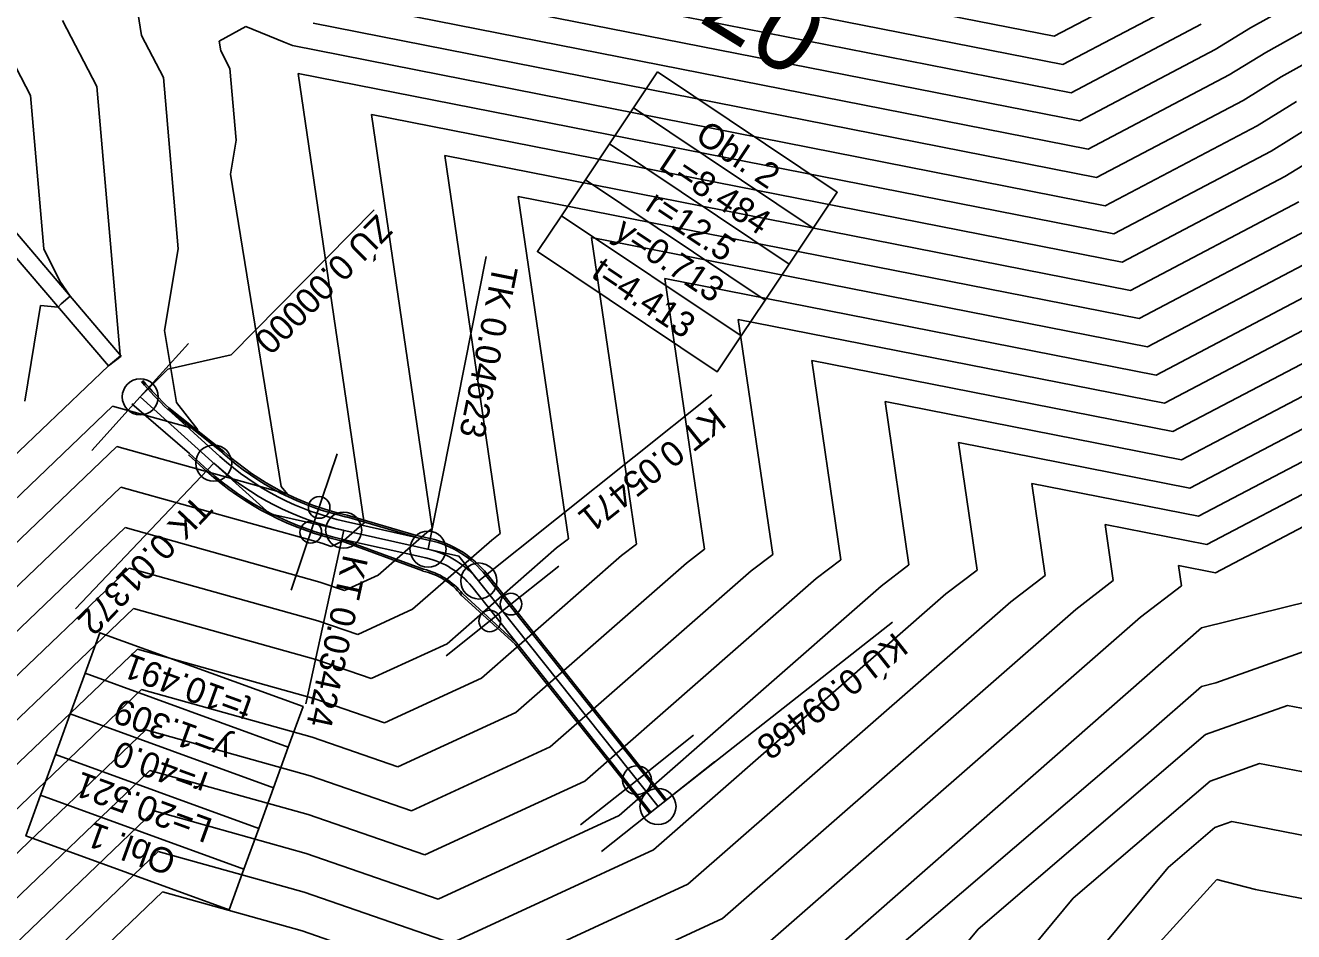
# Model space of a CAD drawing. Extents: x -549394 to -546608, y -1037055 to -1033629.
# Drawn here: x -547395.5 to -547219.5, y -1036140.1 to -1036014.3 of the extents above; entities that cross this region are included whole.
import ezdxf

# ---------------------------------------------------------------- set-up
doc = ezdxf.new("R2010")
doc.units = 0
for name, color, linetype in [('hlavni_vrst', 7, 'Continuous'), ('hrana_L', 7, 'Continuous'), ('norm_vrst', 7, 'Continuous'), ('POLYGONY_SITUACE_PO', 7, 'Continuous'), ('u_sirka_0_5m', 7, 'Continuous'), ('u_sirka_1_5m', 7, 'Continuous'), ('x_navrh_C411', 7, 'Continuous'), ('x_osa_C411', 7, 'Continuous'), ('x_popis_oblouky_C411', 7, 'Continuous'), ('x_popis_pricne_rezy_C411', 7, 'Continuous'), ('x_popis_velky_C411', 7, 'Continuous')]:
    doc.layers.add(name, color=color, linetype=linetype)

msp = doc.modelspace()

# ---------------------------------------------------------------- linework, layer by layer
at = {"layer": 'hlavni_vrst'}
for p, q in [((-547171.43, -1035989.1), (-547223.36, -1036018.08)), ((-547248.01, -1036031.52), (-547352.65, -1036010.92)), ((-547390.31, -1036013.64), (-547385.56, -1036022.8)), ((-547223.36, -1036018.08), (-547228.45, -1036021.22)), ((-547228.45, -1036021.22), (-547248.01, -1036031.52)), ((-547385.56, -1036022.8), (-547382.3, -1036060.1)), ((-547337.27, -1036032.37), (-547329.59, -1036084.85)), ((-547242.13, -1036051.11), (-547337.27, -1036032.37)), ((-547218.78, -1036038.81), (-547242.13, -1036051.11)), ((-547209.1, -1036056.41), (-547236.25, -1036070.69)), ((-547383.95, -1036061.55), (-547529.34, -1036200.56)), ((-547382.26, -1036060.17), (-547383.95, -1036061.55)), ((-547383.95, -1036061.55), (-547383.95, -1036061.55)), ((-547383.95, -1036061.55), (-547383.95, -1036061.55)), ((-547383.95, -1036061.55), (-547383.95, -1036061.55)), ((-547383.95, -1036061.55), (-547383.95, -1036061.55)), ((-547383.95, -1036061.55), (-547383.95, -1036061.55)), ((-547383.95, -1036061.55), (-547383.95, -1036061.55)), ((-547383.95, -1036061.55), (-547383.95, -1036061.55)), ((-547382.3, -1036060.1), (-547382.27, -1036060.15)), ((-547382.27, -1036060.15), (-547382.26, -1036060.17)), ((-547286.38, -1036060.82), (-547282.33, -1036088.47)), ((-547236.25, -1036070.69), (-547286.38, -1036060.82)), ((-547206.64, -1036077.79), (-547230.36, -1036090.28)), ((-547330.76, -1036085.74), (-547341.74, -1036095.35)), ((-547329.59, -1036084.85), (-547330.76, -1036085.74)), ((-547381.07, -1036089.63), (-547506.12, -1036209.19)), ((-547354.88, -1036096.94), (-547381.07, -1036089.63)), ((-547282.33, -1036088.47), (-547285.75, -1036091.08)), ((-547235.49, -1036089.27), (-547235.08, -1036092.1)), ((-547230.36, -1036090.28), (-547235.49, -1036089.27)), ((-547285.75, -1036091.08), (-547317.86, -1036119.19)), ((-547235.08, -1036092.1), (-547240.75, -1036096.43)), ((-547349.34, -1036098.86), (-547354.88, -1036096.94)), ((-547341.74, -1036095.35), (-547349.34, -1036098.86)), ((-547240.75, -1036096.43), (-547293.98, -1036143.02)), ((-547378.19, -1036117.71), (-547482.89, -1036217.82)), ((-547356.25, -1036123.83), (-547378.19, -1036117.71)), ((-547317.86, -1036119.19), (-547340.07, -1036129.43)), ((-547340.07, -1036129.43), (-547356.25, -1036123.83)), ((-547228.09, -1036124.77), (-547230.43, -1036125.6)), ((-547207.41, -1036128.8), (-547228.09, -1036124.77)), ((-547230.43, -1036125.6), (-547236.94, -1036131.17)), ((-547236.94, -1036131.17), (-547248.99, -1036145.66))]:
    msp.add_line(p, q, dxfattribs=at)
at = {"layer": 'hrana_L'}
for p, q in [((-547382.19, -1036060.25), (-547409.46, -1036028.18)), ((-547411.32, -1036029.57), (-547383.95, -1036061.55)), ((-547383.95, -1036061.55), (-547382.19, -1036060.25))]:
    msp.add_line(p, q, dxfattribs=at)
at = {"layer": 'norm_vrst'}
for p, q in [((-547175.57, -1035986.83), (-547225.49, -1036014.69)), ((-547167.28, -1035991.38), (-547221.23, -1036021.48)), ((-547252.72, -1036015.85), (-547341.15, -1035998.44)), ((-547251.54, -1036019.77), (-547344.02, -1036001.56)), ((-547250.37, -1036023.69), (-547346.9, -1036004.68)), ((-547236.19, -1036007.15), (-547252.72, -1036015.85)), ((-547249.19, -1036027.6), (-547349.77, -1036007.8)), ((-547234.25, -1036010.67), (-547251.54, -1036019.77)), ((-547401.29, -1036011.53), (-547394.78, -1036024.05)), ((-547379.86, -1036012.54), (-547379.34, -1036015.76)), ((-547246.84, -1036035.44), (-547355.52, -1036014.04)), ((-547232.32, -1036014.19), (-547250.37, -1036023.69)), ((-547379.34, -1036015.76), (-547376.33, -1036021.55)), ((-547364.89, -1036014.48), (-547368.59, -1036016.53)), ((-547359.56, -1036016.68), (-547364.89, -1036014.48)), ((-547225.49, -1036014.69), (-547230.38, -1036017.7)), ((-547368.59, -1036016.53), (-547368.37, -1036017.88)), ((-547358.4, -1036017.15), (-547359.56, -1036016.68)), ((-547358.4, -1036017.15), (-547358.4, -1036017.15)), ((-547245.66, -1036039.35), (-547358.4, -1036017.15)), ((-547230.38, -1036017.7), (-547249.19, -1036027.6)), ((-547368.37, -1036017.88), (-547367.11, -1036020.3)), ((-547367.11, -1036020.3), (-547366.24, -1036030.25)), ((-547357.62, -1036020.99), (-547348.49, -1036083.4)), ((-547244.48, -1036043.27), (-547357.62, -1036020.99)), ((-547376.33, -1036021.55), (-547374.26, -1036045.33)), ((-547221.23, -1036021.48), (-547226.52, -1036024.74)), ((-547394.78, -1036024.05), (-547392.92, -1036045.34)), ((-547226.52, -1036024.74), (-547246.84, -1036035.44)), ((-547219.1, -1036024.88), (-547224.58, -1036028.26)), ((-547347.44, -1036026.68), (-547339.04, -1036084.12)), ((-547243.31, -1036047.19), (-547347.44, -1036026.68)), ((-547224.58, -1036028.26), (-547245.66, -1036039.35)), ((-547216.97, -1036028.27), (-547222.65, -1036031.78)), ((-547366.24, -1036030.25), (-547367.03, -1036035)), ((-547222.65, -1036031.78), (-547244.48, -1036043.27)), ((-547214.84, -1036031.67), (-547220.71, -1036035.3)), ((-547367.03, -1036035), (-547359.98, -1036078.3)), ((-547220.71, -1036035.3), (-547243.31, -1036047.19)), ((-547327.09, -1036038.06), (-547320.14, -1036085.57)), ((-547240.95, -1036055.02), (-547327.09, -1036038.06)), ((-547216.84, -1036042.33), (-547240.95, -1036055.02)), ((-547316.91, -1036043.75), (-547310.69, -1036086.3)), ((-547239.78, -1036058.94), (-547316.91, -1036043.75)), ((-547392.92, -1036045.34), (-547390.7, -1036049.8)), ((-547374.26, -1036045.33), (-547376.15, -1036056.66)), ((-547214.91, -1036045.85), (-547239.78, -1036058.94)), ((-547306.73, -1036049.44), (-547301.23, -1036087.02)), ((-547238.6, -1036062.86), (-547306.73, -1036049.44)), ((-547212.97, -1036049.37), (-547238.6, -1036062.86)), ((-547390.7, -1036049.8), (-547389.27, -1036051.92)), ((-547390.52, -1036052.95), (-547390.9, -1036053.43)), ((-547389.27, -1036051.92), (-547390.52, -1036052.95)), ((-547211.04, -1036052.89), (-547237.42, -1036066.77)), ((-547393.38, -1036053.21), (-547395.55, -1036066.47)), ((-547390.9, -1036053.43), (-547393.38, -1036053.21)), ((-547296.56, -1036055.13), (-547291.78, -1036087.75)), ((-547237.42, -1036066.77), (-547296.56, -1036055.13)), ((-547376.15, -1036056.66), (-547374.52, -1036066.65)), ((-547207.17, -1036059.92), (-547235.07, -1036074.61)), ((-547205.23, -1036063.44), (-547233.89, -1036078.53)), ((-547374.52, -1036066.65), (-547371.54, -1036070.47)), ((-547276.2, -1036066.51), (-547272.88, -1036089.2)), ((-547235.07, -1036074.61), (-547276.2, -1036066.51)), ((-547203.3, -1036066.96), (-547232.71, -1036082.44)), ((-547383.37, -1036067.17), (-547524.69, -1036202.29)), ((-547371.54, -1036070.47), (-547383.37, -1036067.17)), ((-547201.37, -1036070.48), (-547231.54, -1036086.36)), ((-547266.02, -1036072.2), (-547263.43, -1036089.92)), ((-547233.89, -1036078.53), (-547266.02, -1036072.2)), ((-547382.8, -1036072.78), (-547520.05, -1036204.01)), ((-547359.12, -1036079.39), (-547382.8, -1036072.78)), ((-547382.22, -1036078.4), (-547515.4, -1036205.74)), ((-547354.33, -1036086.19), (-547382.22, -1036078.4)), ((-547359.98, -1036078.3), (-547359.12, -1036079.39)), ((-547255.85, -1036077.89), (-547253.98, -1036090.65)), ((-547232.71, -1036082.44), (-547255.85, -1036077.89)), ((-547381.64, -1036084.01), (-547510.76, -1036207.47)), ((-547354.6, -1036091.56), (-547381.64, -1036084.01)), ((-547348.76, -1036083.6), (-547351.29, -1036085.82)), ((-547348.49, -1036083.4), (-547348.76, -1036083.6)), ((-547339.04, -1036084.12), (-547339.76, -1036084.67)), ((-547245.67, -1036083.58), (-547244.53, -1036091.37)), ((-547231.54, -1036086.36), (-547245.67, -1036083.58)), ((-547353.05, -1036086.63), (-547354.33, -1036086.19)), ((-547351.29, -1036085.82), (-547353.05, -1036086.63)), ((-547339.76, -1036084.67), (-547346.52, -1036090.59)), ((-547320.14, -1036085.57), (-547321.76, -1036086.81)), ((-547310.69, -1036086.3), (-547312.76, -1036087.88)), ((-547321.76, -1036086.81), (-547336.97, -1036100.12)), ((-547312.76, -1036087.88), (-547332.19, -1036104.89)), ((-547301.23, -1036087.02), (-547303.76, -1036088.94)), ((-547291.78, -1036087.75), (-547294.76, -1036090.01)), ((-547303.76, -1036088.94), (-547327.42, -1036109.66)), ((-547272.88, -1036089.2), (-547276.75, -1036092.15)), ((-547263.43, -1036089.92), (-547267.75, -1036093.22)), ((-547351.19, -1036092.74), (-547354.6, -1036091.56)), ((-547346.52, -1036090.59), (-547351.19, -1036092.74)), ((-547294.76, -1036090.01), (-547322.64, -1036114.42)), ((-547253.98, -1036090.65), (-547258.75, -1036094.29)), ((-547244.53, -1036091.37), (-547249.75, -1036095.36)), ((-547276.75, -1036092.15), (-547313.09, -1036123.96)), ((-547267.75, -1036093.22), (-547308.31, -1036128.72)), ((-547258.75, -1036094.29), (-547303.54, -1036133.49)), ((-547217.14, -1036094.19), (-547232.29, -1036097.92)), ((-547380.49, -1036095.24), (-547501.47, -1036210.92)), ((-547355.15, -1036102.32), (-547380.49, -1036095.24)), ((-547249.75, -1036095.36), (-547298.76, -1036138.26)), ((-547232.29, -1036097.92), (-547263.21, -1036125.03)), ((-547336.97, -1036100.12), (-547347.49, -1036104.97)), ((-547379.92, -1036100.86), (-547496.83, -1036212.64)), ((-547355.43, -1036107.7), (-547379.92, -1036100.86)), ((-547216.52, -1036100.64), (-547230.31, -1036105.55)), ((-547347.49, -1036104.97), (-547355.15, -1036102.32)), ((-547332.19, -1036104.89), (-547345.63, -1036111.08)), ((-547230.31, -1036105.55), (-547232.29, -1036106.04)), ((-547379.34, -1036106.47), (-547492.18, -1036214.37)), ((-547355.7, -1036113.07), (-547379.34, -1036106.47)), ((-547232.29, -1036106.04), (-547240.02, -1036112.82)), ((-547345.63, -1036111.08), (-547355.43, -1036107.7)), ((-547220.38, -1036108.68), (-547231.74, -1036112.73)), ((-547208.93, -1036110.91), (-547220.38, -1036108.68)), ((-547327.42, -1036109.66), (-547343.78, -1036117.2)), ((-547378.76, -1036112.09), (-547487.54, -1036216.1)), ((-547355.98, -1036118.45), (-547378.76, -1036112.09)), ((-547231.74, -1036112.73), (-547263.28, -1036139.71)), ((-547343.78, -1036117.2), (-547355.7, -1036113.07)), ((-547322.64, -1036114.42), (-547341.92, -1036123.31)), ((-547240.02, -1036112.82), (-547276.46, -1036143.97)), ((-547224.23, -1036116.72), (-547231.08, -1036119.17)), ((-547208.17, -1036119.85), (-547224.23, -1036116.72)), ((-547341.92, -1036123.31), (-547355.98, -1036118.45)), ((-547231.08, -1036119.17), (-547250.11, -1036135.44)), ((-547377.61, -1036123.32), (-547478.25, -1036219.55)), ((-547356.53, -1036129.21), (-547377.61, -1036123.32)), ((-547313.09, -1036123.96), (-547338.22, -1036135.54)), ((-547263.21, -1036125.03), (-547289.21, -1036147.79)), ((-547377.03, -1036128.94), (-547473.61, -1036221.27)), ((-547356.81, -1036134.59), (-547377.03, -1036128.94)), ((-547338.22, -1036135.54), (-547356.53, -1036129.21)), ((-547308.31, -1036128.72), (-547336.36, -1036141.66)), ((-547303.54, -1036133.49), (-547334.51, -1036147.77)), ((-547230.16, -1036132.81), (-547254.65, -1036159.77)), ((-547224.8, -1036134.2), (-547230.16, -1036132.81)), ((-547376.46, -1036134.55), (-547468.96, -1036223)), ((-547357.08, -1036139.96), (-547376.46, -1036134.55)), ((-547336.36, -1036141.66), (-547356.81, -1036134.59)), ((-547250.11, -1036135.44), (-547274.08, -1036164.24)), ((-547206.65, -1036137.74), (-547224.8, -1036134.2)), ((-547298.76, -1036138.26), (-547332.65, -1036153.88)), ((-547334.51, -1036147.77), (-547357.08, -1036139.96)), ((-547263.28, -1036139.71), (-547279.13, -1036158.75))]:
    msp.add_line(p, q, dxfattribs=at)
at = {"layer": 'POLYGONY_SITUACE_PO'}
for centre in [(-547379.53, -1036065.87), (-547369.34, -1036075.06), (-547351.31, -1036084.38), (-547339.61, -1036087), (-547332.56, -1036091.42), (-547307.7, -1036122.71)]:
    msp.add_circle(centre, 2.5, dxfattribs=at)
at = {"layer": 'u_sirka_0_5m'}
msp.add_circle((-547310.61, -1036119.05), 2, dxfattribs=at)
at = {"layer": 'u_sirka_1_5m'}
for centre in [(-547354.71, -1036081.22), (-547355.87, -1036084.65), (-547328.1, -1036094.63), (-547331.04, -1036096.97)]:
    msp.add_circle(centre, 1.5, dxfattribs=at)
at = {"layer": 'x_navrh_C411'}
for p, q in [((-547380.68, -1036066.85), (-547372.69, -1036073.72)), ((-547375.72, -1036067.6), (-547368.51, -1036074.13)), ((-547368.09, -1036073.66), (-547375.72, -1036067.6)), ((-547367.92, -1036073.47), (-547375.56, -1036067.41)), ((-547372.86, -1036073.91), (-547370.35, -1036076.17)), ((-547372.69, -1036073.72), (-547370.18, -1036075.99)), ((-547350.9, -1036082.54), (-547341.28, -1036085.35)), ((-547350.84, -1036082.3), (-547341.22, -1036085.1)), ((-547351.04, -1036083.16), (-547339.34, -1036085.78)), ((-547340.31, -1036090.03), (-547351.66, -1036085.84)), ((-547351.59, -1036085.6), (-547339.89, -1036088.22)), ((-547340.24, -1036089.79), (-547351.59, -1036085.6)), ((-547331.58, -1036090.64), (-547306.72, -1036121.93)), ((-547334.99, -1036093.37), (-547327.5, -1036100.2)), ((-547334.8, -1036093.2), (-547327.32, -1036100.03)), ((-547333.54, -1036092.2), (-547308.68, -1036123.49))]:
    msp.add_line(p, q, dxfattribs=at)
for points in [[(-547341.22, -1036085.1), (-547339.29, -1036085.54)], [(-547331.39, -1036090.49), (-547306.52, -1036121.78)], [(-547327.5, -1036100.2), (-547308.87, -1036123.64)]]:
    msp.add_lwpolyline(points, dxfattribs=at)
for centre, radius, start, end in [((-547341.29, -1036031.35), 50, 220.3973, 226.4763), ((-547341.29, -1036031.35), 49.75, 220.3973, 226.4635), ((-547342.56, -1036045.35), 38.12, 227.9685, 257.3622), ((-547342.56, -1036045.35), 37.87, 227.9566, 257.374), ((-547342.56, -1036045.35), 38.75, 227.9685, 257.3622), ((-547342.56, -1036045.35), 41.5, 227.9685, 257.3391), ((-547342.56, -1036045.35), 41.25, 227.9685, 257.3622), ((-547342.35, -1036099.2), 13.75, 38.4742, 77.3622), ((-547342.35, -1036099.2), 14, 38.4742, 77.3622), ((-547342.35, -1036099.2), 9.64, 38.4742, 77.3622), ((-547342.35, -1036099.2), 11.25, 38.4742, 77.3622), ((-547342.35, -1036099.2), 9.39, 38.353, 77.4634)]:
    msp.add_arc(centre, radius, start, end, dxfattribs=at)
at = {"layer": 'x_osa_C411'}
for points in [[(-547379.53, -1036065.87), (-547361.55, -1036082.08)], [(-547361.55, -1036082.08), (-547335.31, -1036087.97), (-547307.7, -1036122.71)]]:
    msp.add_lwpolyline(points, dxfattribs=at)
for centre, radius, start, end in [((-547342.56, -1036045.35), 40, 227.9685, 257.3622), ((-547342.35, -1036099.2), 12.5, 38.4742, 77.3622)]:
    msp.add_arc(centre, radius, start, end, dxfattribs=at)
at = {"layer": 'x_popis_oblouky_C411'}
for points in [[(-547307.75, -1036020.8), (-547282.82, -1036037.48), (-547286.16, -1036042.47), (-547311.09, -1036025.78)], [(-547311.09, -1036025.78), (-547286.16, -1036042.47), (-547289.49, -1036047.45), (-547314.43, -1036030.77)], [(-547314.43, -1036030.77), (-547289.49, -1036047.45), (-547292.83, -1036052.44), (-547317.76, -1036035.76)], [(-547317.76, -1036035.76), (-547292.83, -1036052.44), (-547296.17, -1036057.43), (-547321.1, -1036040.74)], [(-547321.1, -1036040.74), (-547296.17, -1036057.43), (-547299.5, -1036062.41), (-547324.44, -1036045.73)], [(-547359, -1036114.49), (-547387.19, -1036104.23), (-547385.13, -1036098.59), (-547356.94, -1036108.85)], [(-547361.05, -1036120.13), (-547389.24, -1036109.87), (-547387.19, -1036104.23), (-547359, -1036114.49)], [(-547363.1, -1036125.77), (-547391.29, -1036115.5), (-547389.24, -1036109.87), (-547361.05, -1036120.13)], [(-547365.16, -1036131.41), (-547393.35, -1036121.14), (-547391.29, -1036115.5), (-547363.1, -1036125.77)], [(-547367.21, -1036137.04), (-547395.4, -1036126.78), (-547393.35, -1036121.14), (-547365.16, -1036131.41)]]:
    msp.add_lwpolyline(points, close=True, dxfattribs=at)
for points in [[(-547379.53, -1036065.87), (-547375.72, -1036062.04), (-547366.94, -1036060.05), (-547347.06, -1036039.92)], [(-547331.55, -1036046.42), (-547339.61, -1036087)], [(-547300.22, -1036065.61), (-547332.56, -1036091.42)], [(-547369.34, -1036075.06), (-547388.51, -1036095.27)], [(-547351.31, -1036084.38), (-547356.57, -1036108.47)], [(-547275.17, -1036097.15), (-547307.7, -1036122.71)]]:
    msp.add_lwpolyline(points, dxfattribs=at)
at = {"layer": 'x_popis_pricne_rezy_C411'}
for points in [[(-547372.84, -1036058.45), (-547379.53, -1036065.87), (-547386.23, -1036073.3)], [(-547352.19, -1036073.76), (-547355.39, -1036083.23), (-547358.6, -1036092.71)], [(-547321.44, -1036089.34), (-547329.27, -1036095.56), (-547337.1, -1036101.78)], [(-547302.78, -1036112.83), (-547310.61, -1036119.05), (-547318.44, -1036125.27)], [(-547299.87, -1036116.49), (-547307.7, -1036122.71), (-547315.53, -1036128.93)]]:
    msp.add_lwpolyline(points, dxfattribs=at)

# ---------------------------------------------------------------- texts
at = {"layer": 'x_popis_oblouky_C411'}
for s, rotation, p in [('Obl. 2', 326.2325, (-547302.74, -1036030.23)), ('L=8.484', 326.2325, (-547307.78, -1036034.08)), ('r=12.5', 326.2325, (-547309.66, -1036039.83)), ('ZÚ 0.00000', 225.2267, (-547346.7, -1036040.41)), ('y=0.713', 326.2325, (-547314.01, -1036043.61)), ('t=4.413', 326.2325, (-547317.16, -1036049.15)), ('TK 0.04623', 258.7591, (-547330.56, -1036047.42)), ('KT 0.05471', 218.5908, (-547300.14, -1036067.04)), ('TK 0.01372', 226.5188, (-547371.83, -1036079.24)), ('KT 0.03424', 257.6857, (-547351.32, -1036087.62)), ('KÚ 0.09468', 218.1601, (-547274.88, -1036098.41)), ('t=10.491', 160.0167, (-547363.74, -1036107.66)), ('y=1.309', 160.0167, (-547366.57, -1036113.39)), ('r=40.0', 160.0167, (-547369.89, -1036118.1)), ('L=20.521', 160.0167, (-547369.26, -1036124.53)), ('Obl. 1', 160.0167, (-547374.32, -1036129.07))]:
    msp.add_text(s, height=3.5, rotation=rotation, dxfattribs=at).set_placement(p)
at = {"layer": 'x_popis_velky_C411'}
msp.add_text('C411,P3/20', height=10.5, rotation=328.2284, dxfattribs=at).set_placement((-547352.04, -1035982.85))

doc.saveas('drawing.dxf')
